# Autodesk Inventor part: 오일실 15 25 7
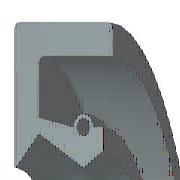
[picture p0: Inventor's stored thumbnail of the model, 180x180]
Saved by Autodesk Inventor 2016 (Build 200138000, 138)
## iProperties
Created: 2012-02
Part Number: 오일실 15 25 7
Material: 고무
Description: 오일-실
Document SubType Name: Modeling
Standard: KS B 2804
Designer: mduedu
Standards Organization: KS
Language: ko-KR
Size Designation: D - 15 25 7
Categories: <MemberInstance><Categories><Category DisplayName="샤프트 부품" InternalName="7f7aeb1f-a693-4053-b835-cee3144e0d98" Mnemonic="SHFT"><Category DisplayName="실링" Intern
Density: 0.93 g/cm^3
Appearance: 고무 - 검은색 - 버전 1.1
IsCustomPart: 1
Author: mduedu
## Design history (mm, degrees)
revolve "본체" stored, may be unused: angle "d17" = 90 deg
revolve "스프링1" stored, may be unused: angle "d18" = 90 deg
body "Solid1"
sketch "스케치1"
  geometry: L1 (0, 12.5)-(7, 12.5); L2 (7, 10.75)-(1.75, 10.75); L3 (1.75, 9.25)-(4.9, 7.5); L4 (4.9, 7.5)-(0, 7.5); L5 (0, 0)-(9.586, 0) reference; L6 (4.9, 7.5)-(6.3, 8.375); L7 (0, 18)-(0, -3) reference; L8 (-1.941, 0)-(11.507, 0) reference; L9 (4.2, 9.6)-(1.75, 10.09); L10 (1.75, 10.09)-(1.75, 10.75); L11 (0, 12.5)-(0, 7.588); L12 (4.9, 7.5)-(0, 7.5); L13 (1.75, 9.25)-(0.152, 7.528); L14 (7, 12.5)-(7, 10.75); L15 (5.6, 9.6)-(6.3, 9.6); L16 (6.3, 9.6)-(6.3, 8.375); C1 r 0.455 at (4.9, 9.6); A1 r 0.7 centre (4.9, 9.6) between (5.6, 9.6) and (4.2, 9.6); A2 r 0.088 centre (0.088, 7.588) between (0, 7.588) and (0.152, 7.528); 1 further point
  constraints: 28 end point, 5 horizontal alignment, 5 point on line, 4 point on circle, 4 vertical alignment, 3 centre point, 3 tangent, 2 collinear, 2 horizontal, 2 perpendicular, 1 coincident, 1 parallel
  dimensions: "d0" = 25 diameter of L1 L5 (= SD2); "d1" = 1.75 distance of L1.end L2.start (= SD); "d2" = 0.91 diameter of C1 (= SPDI); "d3" = 1.4 diameter of A1 (= SPDA); "d4" = 15 diameter of L3.end L5 (= NND); "d5" = 18.5 diameter of L3.start L5 (= TKDM); "d7" = 20.18 diameter of L9.end L5 (= TKDM + 0.24 x SWDT); "d8" = 1.75 distance between parallel lines of L11 L10 (= SD); "d9" = 4.9 distance from line of L11 C1.centre (= SPDST); "d10" = 19.2 diameter of C1.centre L5 (= HLDM); "d11" = 0.0875 radius of A2 (= 0.25 x LAB); "d12" = 6.3 distance between parallel lines of L11 L16 (= SDI); "d13" = 16.75 diameter of L6.end L5 (= ABDM); "d14" = 7 distance from line of L11 L1.end (= SWDT)
fillet "모깎기1" dims "d6" = 0.3 (= RR)
other parameters: "SD2" = 25 [user parameter; used in 1 equation term], "SWDT" = 7 [user parameter; used in 2 equation terms], "RR" = 0.3 [user parameter; used in 1 equation term], "SD" = 1.75 [user parameter; used in 2 equation terms], "NND" = 15 [user parameter; used in 1 equation term], "SPDA" = 1.4 [user parameter; used in 1 equation term], "SPDI" = 0.91 [user parameter; used in 1 equation term], "TKDM" = 18.5 [user parameter; used in 2 equation terms], "HLDM" = 19.2 [user parameter; used in 1 equation term], "ABDM" = 16.75 [user parameter; used in 1 equation term], "SDI" = 6.3 [user parameter; used in 1 equation term], "SPDST" = 4.9 [user parameter; used in 1 equation term], "LAB" = 0.35 [user parameter; used in 1 equation term], "d15" = 0, "d16" = 0, "d19" = 0
